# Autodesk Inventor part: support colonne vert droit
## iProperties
Shininess: 64.0
Length Units: 11269
Angle Units: 11279
Time Units: 11290
Mass Units: 11283
Length Display Precision: 3
Angle Display Precision: 2
Compacted: True
Part Number: support colonne vert droit
Document SubType Name: Modeling
Created: 2005-01
Material: Par défaut
Designer: LEGERET Philippe
Density: 0.0
Volumn: 0.0
Area: 0.0
PropertySet Name: Model Information
Control State: 0
Master: False
Checked Out: False
Author: LEGERET Philippe
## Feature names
1. Extrusion1
2. Perçage1 [Hole]
3. Perçage2 [Hole]
4. Chanfrein4 [Chamfer]
5. Chanfrein5 [Chamfer]
6. Chanfrein6 [Chamfer]
